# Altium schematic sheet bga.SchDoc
size A4
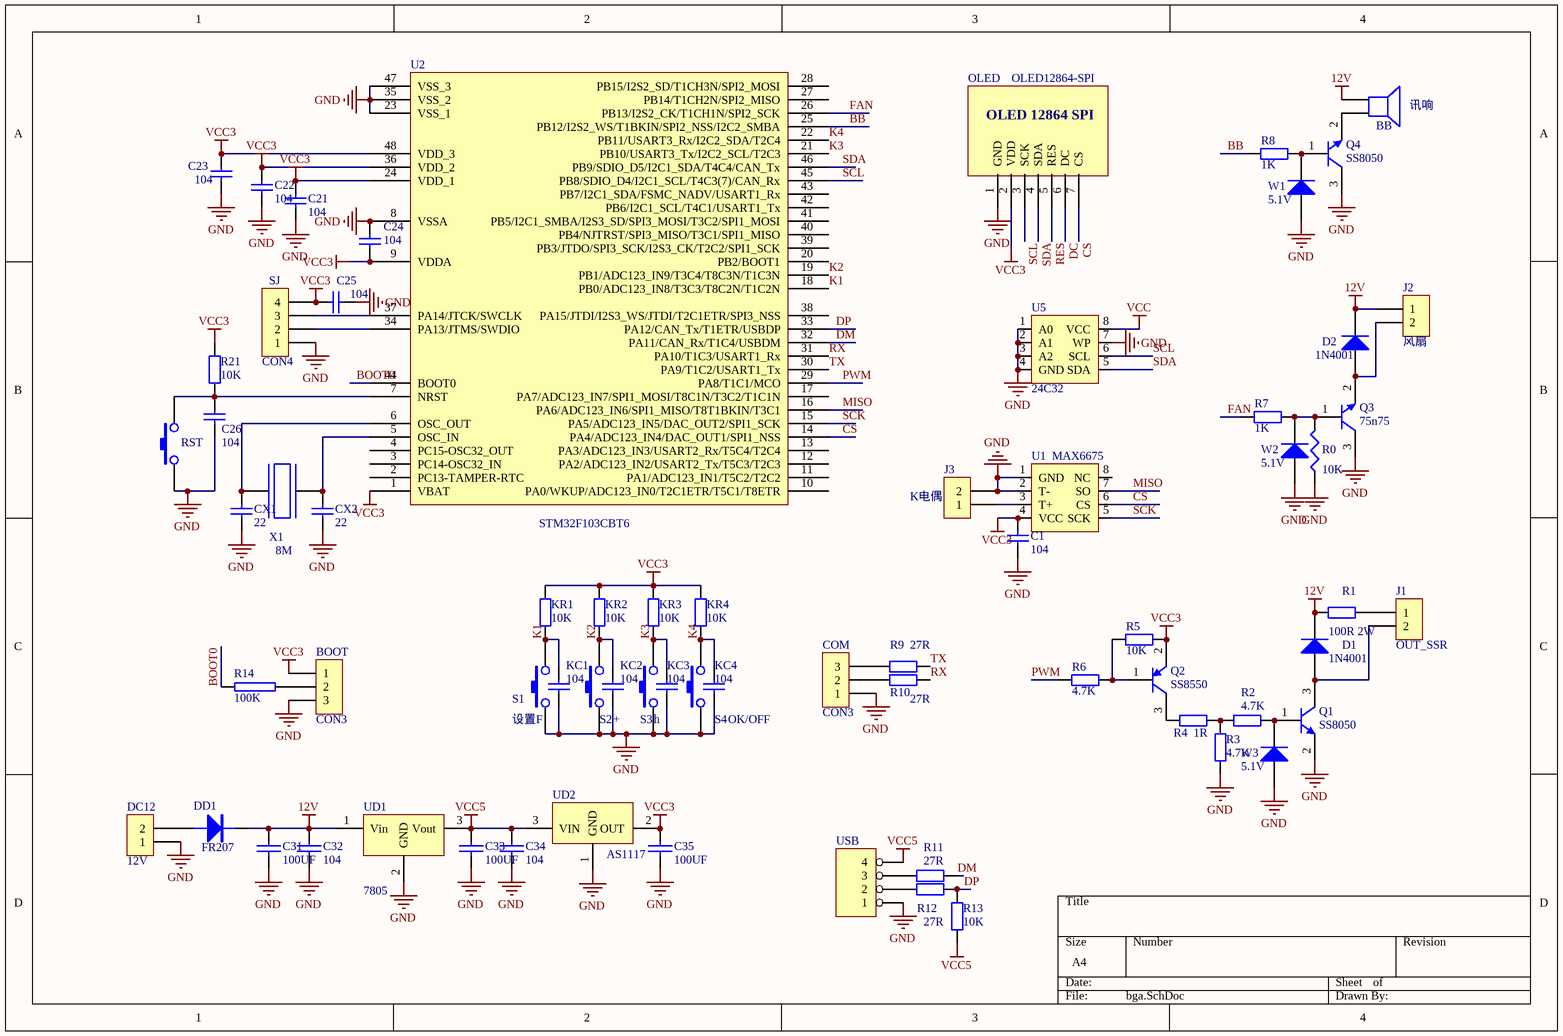
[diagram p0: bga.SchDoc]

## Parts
BOOT  CON3  [SIP03]
C1  104  [0805]
C21  104  [0805]
C22  104  [0805]
C23  104  [0805]
C24  104  [0805]
C25  104  [0805]
C26  104  [0805]
C31  100UF  [C-RB-S10]
C32  104  [0805]
C33  100UF  [C-RB-S10]
C34  104  [0805]
C35  100UF  [C-RB-S10]
COM  CON3  [DC-3]
CX1  22  [0805]
CX2  22  [0805]
D1  Type: 1N4001  [DIODE-SMA]  (hidden comment: Diode)
D2  Type: 1N4001  [DIODE-SMA]  (hidden comment: Diode)
DC12  12V  [DC-2]
DD1  FR207  [DIODE-SMA]
J1  OUT_SSR  [J-7620-2]
J2  风扇  [J-7620-2]
J3  K电偶  [J-7620-2]
KC1  104  [0805]
KC2  104  [0805]
KC3  104  [0805]
KC4  104  [0805]
KR1  value 10K  [0805]  (hidden comment: Res1)
KR2  value 10K  [0805]  (hidden comment: Res1)
KR3  value 10K  [0805]  (hidden comment: Res1)
KR4  value 10K  [0805]  (hidden comment: Res1)
OLED  OLED12864-SPI  [RP18]
Q1  SS8050  [SOT-23]
Q2  SS8550  [SOT-23]
Q3  75n75  [SOT-252-3]
Q4  SS8050  [SOT-23]
R0  10K
R1  value 100R 2W  [AXIAL-0.8]  (hidden comment: Res1)
R2  value 4.7K  [0805]  (hidden comment: Res1)
R3  value 4.7K  [0805]  (hidden comment: Res1)
R4  value 1R  [0805]  (hidden comment: Res1)
R5  value 10K  [0805]  (hidden comment: Res1)
R6  value 4.7K  [0805]  (hidden comment: Res1)
R7  value 1K  [0805]  (hidden comment: Res1)
R8  value 1K  [0805]  (hidden comment: Res1)
R9  value 27R  [0805]  (hidden comment: Res1)
R10  value 27R  [0805]  (hidden comment: Res1)
R11  value 27R  [0805]  (hidden comment: Res1)
R12  value 27R  [0805]  (hidden comment: Res1)
R13  value 10K  [0805]  (hidden comment: Res1)
R14  100K  [0805]
R21  value 10K  [0805]  (hidden comment: Res1)
RST  (no value)  [KEY3X6]
S1  设置F  [KEY12X12]
S2  +  [KEY12X12]
S3  һ  [KEY12X12]
S4  OK/OFF  [KEY12X12]
SJ  CON4  [SIP04]
U1  MAX6675  [SO8]
U2  STM32F103CBT6  [TQFP-48]
U5  24C32  [SO8]
UD1  7805  [SOT-252-4]
UD2  AS1117  [SOT-223-4]
USB  4 HEADER  [SIP04]  (value not drawn)
W1  5.1V  [DIODE-SMA]
W2  5.1V  [DIODE-SMA]
W3  5.1V  [DIODE-SMA]
X1  8M  [XTAL49S_DIP]
讯响  BB  [BUZZ 12X9]

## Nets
12V: C31.1 C32.1 D1.2(K) D2.2(K) DD1.2 J2.1 R1.1 UD1.1(Vin) 讯响.1
GND: BOOT.3 C1.1 C21.1 C22.1 C23.1 C24.2 C25.1 C26.1 C31.2 C32.2 C33.2 C34.2 C35.2 COM.1 CX1.1 CX2.1 DC12.1 J3.2 KC1.1 KC2.1 KC3.1 KC4.1 OLED.1(GND) Q1.2(E) Q3.3(C) Q4.3(C) R0.1 R3.1 RST.1 S1.1 S2.1 S3.1 S4.1 SJ.1 U1.1(GND) U1.2(T-) U2.8(VSSA) U2.23(VSS_1) U2.35(VSS_2) U2.47(VSS_3) U5.1(A0) U5.2(A1) U5.3(A2) U5.4(GND) U5.7(WP) UD1.2(GND) UD2.1(GND) USB.1 W1.1(A) W2.1(A) W3.1(A)
VCC: U5.8(VCC)
VCC3: BOOT.1 C1.2 C21.2 C22.2 C23.2 C24.1 C25.2 C35.1 KR1.1 KR2.1 KR3.1 KR4.1 OLED.2(VDD) Q2.2(E) R5.2 R21.2 SJ.4 U1.4(VCC) U2.1(VBAT) U2.9(VDDA) U2.24(VDD_1) U2.36(VDD_2) U2.48(VDD_3) UD2.2(OUT)
VCC5: C33.1 C34.1 R13.2 UD1.3(Vout) UD2.3(VIN) USB.4
BB: R8.1 U2.25(PB12/I2S2_WS/T1BKIN/SPI2_NSS/I2C2_SMBA)
BOOT0: R14.1 U2.44(BOOT0)
CS: OLED.7(CS) U1.6(CS) U2.14(PA4/ADC123_IN4/DAC_OUT1/SPI1_NSS)
DC: OLED.6(DC)
DM: R11.1 U2.32(PA11/CAN_Rx/T1C4/USBDM)
DP: R12.1 R13.1 U2.33(PA12/CAN_Tx/T1ETR/USBDP)
FAN: R7.1 U2.26(PB13/I2S2_CK/T1CH1N/SPI2_SCK)
K1: KC1.2 KR1.2 S1.2 U2.18(PB0/ADC123_IN8/T3C3/T8C2N/T1C2N)
K2: KC2.2 KR2.2 S2.2 U2.19(PB1/ADC123_IN9/T3C4/T8C3N/T1C3N)
K3: KC3.2 KR3.2 S3.2 U2.21(PB10/USART3_Tx/I2C2_SCL/T2C3)
K4: KC4.2 KR4.2 S4.2 U2.22(PB11/USART3_Rx/I2C2_SDA/T2C4)
MISO: U1.7(SO) U2.16(PA6/ADC123_IN6/SPI1_MISO/T8T1BKIN/T3C1)
PWM: R6.2 U2.29(PA8/T1C1/MCO)
RES: OLED.5(RES)
RX: R10.1 U2.31(PA10/T1C3/USART1_Rx)
SCK: U1.5(SCK) U2.15(PA5/ADC123_IN5/DAC_OUT2/SPI1_SCK)
SCL: OLED.3(SCK) U2.45(PB8/SDIO_D4/I2C1_SCL/T4C3(7)/CAN_Rx) U5.6(SCL)
SDA: OLED.4(SDA) U2.46(PB9/SDIO_D5/I2C1_SDA/T4C4/CAN_Tx) U5.5(SDA)
TX: R9.1 U2.30(PA9/T1C2/USART1_Tx)
NetBOOT_2: BOOT.2 R14.2
NetC26_2: C26.2 R21.1 RST.2 U2.7(NRST)
NetCOM_2: COM.2 R10.2
NetCOM_3: COM.3 R9.2
NetCX1_2: CX1.2 U2.6(OSC_OUT) X1.2
NetCX2_2: CX2.2 U2.5(OSC_IN) X1.1
NetD1_1: D1.1(A) J1.2 Q1.3(C)
NetD2_1: D2.1(A) J2.2 Q3.2(E)
NetDC12_2: DC12.2 DD1.1
NetJ1_1: J1.1 R1.2
NetJ3_1: J3.1 U1.3(T+)
NetQ1_1: Q1.1(B) R2.2 W3.2(K)
NetQ2_1: Q2.1(B) R5.1 R6.1
NetQ2_3: Q2.3(C) R4.1
NetQ3_1: Q3.1(B) R0.2 R7.2 W2.2(K)
NetQ4_1: Q4.1(B) R8.2 W1.2(K)
NetQ4_2: Q4.2(E) 讯响.2
NetR2_1: R2.1 R3.2 R4.2
NetR11_2: R11.2 USB.3
NetR12_2: R12.2 USB.2
NetSJ_2: SJ.2 U2.34(PA13/JTMS/SWDIO)
NetSJ_3: SJ.3 U2.37(PA14/JTCK/SWCLK)

Not connected (* = marked no-connect by the designer): U1 8(NC); U2 2(PC13-TAMPER-RTC) 3(PC14-OSC32_IN) 4(PC15-OSC32_OUT) 10(PA0/WKUP/ADC123_IN0/T2C1ETR/T5C1/T8ETR) 11(PA1/ADC123_IN1/T5C2/T2C2) 12(PA2/ADC123_IN2/USART2_Tx/T5C3/T2C3) 13(PA3/ADC123_IN3/USART2_Rx/T5C4/T2C4) 17(PA7/ADC123_IN7/SPI1_MOSI/T8C1N/T3C2/T1C1N) 20(PB2/BOOT1) 27(PB14/T1CH2N/SPI2_MISO) 28(PB15/I2S2_SD/T1CH3N/SPI2_MOSI) 38(PA15/JTDI/I2S3_WS/JTDI/T2C1ETR/SPI3_NSS) 39(PB3/JTDO/SPI3_SCK/I2S3_CK/T2C2/SPI1_SCK) 40(PB4/NJTRST/SPI3_MISO/T3C1/SPI1_MISO) 41(PB5/I2C1_SMBA/I2S3_SD/SPI3_MOSI/T3C2/SPI1_MOSI) 42(PB6/I2C1_SCL/T4C1/USART1_Tx) 43(PB7/I2C1_SDA/FSMC_NADV/USART1_Rx)

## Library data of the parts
BOOT COM = CON3: Connector
C1 C21-C26 CX1 CX2 KC1-KC4 = Cap: Capacitor; Value: 100pF
C31-C35 = CAP: Capacitor
D1 D2 W1-W3 = Diode: 二极管
DC12 J1-J3 = CON2: Connector
DD1 = DIODE
KR1-KR4 R1-R13 R21 = Res1: 贴片电阻
Q1 Q3 Q4 = SS8050: NPN贴片三极管
Q2 = SS8550: PNP贴片三极管
R0 = RES1
R14 = RES2
RST S1-S4 = SW-PB
SJ = CON4: Connector
U1 = MAX6675: K电偶转换
U2 = STM32F103C: STM32单片机48引脚
U5 = 24C**: 存储器
USB = 4 HEADER: 4 Pin Header
X1 = XTAL
讯响 = SPEAKER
